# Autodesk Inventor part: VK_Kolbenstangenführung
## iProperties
Created: 2003-12
Part Number: VK_Kolbenstangenführung
Material: Messing (weiches, gelbes Messing)
Document SubType Name: Modellieren
Designer: Ulrich
Control State: 0
Master: False
Checked Out: False
Shininess: 20.0
Angle Display Precision: 2
Document Length Units: 11269
Document Angle Units: 11279
Document Time Units: 11290
Document Mass Units: 11283
Document Length Units Precision: 3
Document Angle Units Precision: 2
Density: 0.0
Volumn: 0.0
Area: 0.0
PropertySet Name: Model Information
Author: Ulrich
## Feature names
1. Extrusion_Vierkant
2. Bohrung_Zapfen [Hole]
3. Extrusion_Zapfen
4. Extrusion3
